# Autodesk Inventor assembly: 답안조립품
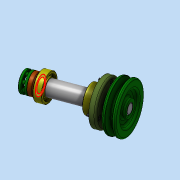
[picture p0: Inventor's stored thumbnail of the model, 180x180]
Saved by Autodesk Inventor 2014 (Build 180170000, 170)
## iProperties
Created: 2017-09
Part Number: 답안조립품
Document SubType Name: Assembly
Designer: user
Author: user
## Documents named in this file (12)
- C:\Users\user\Desktop\470908V1007\답안조립품.iam
- C:\Users\user\Desktop\470908V1007\본체.ipt
- C:\Users\user\Desktop\470908V1007\오일 실 20x35x7.ipt
- C:\Users\user\Desktop\470908V1007\축.ipt
- C:\Users\user\Desktop\470908V1007\커버.ipt
- C:\Users\user\Desktop\470908V1007\키 5 x 5 x 16.ipt
- C:\Users\user\Desktop\470908V1007\V벨트풀리.ipt
- C:\Users\user\Desktop\470908V1007\멈춤나사 M3x8.ipt
- C:\Users\user\Desktop\470908V1007\베어링 6004.ipt
- C:\Users\user\Desktop\470908V1007\베어링 51202.ipt
- C:\Users\user\Desktop\470908V1007\볼트 M4 x 12.ipt
- C:\Users\user\Desktop\470908V1007\어댑터슬리브.ipt
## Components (1 placed, 1 different names)
1. V벨트풀리:1 — Mate:3, Angle:2, Flush:1, Mate:4
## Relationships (4: Mate 2, Angle 1, Flush 1)
- Mate:3: V벨트풀리:1
- Angle:2: V벨트풀리:1
- Flush:1: V벨트풀리:1
- Mate:4: V벨트풀리:1
